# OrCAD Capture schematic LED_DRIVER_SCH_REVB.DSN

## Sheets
1 P02: P2W Led Driver Diagram
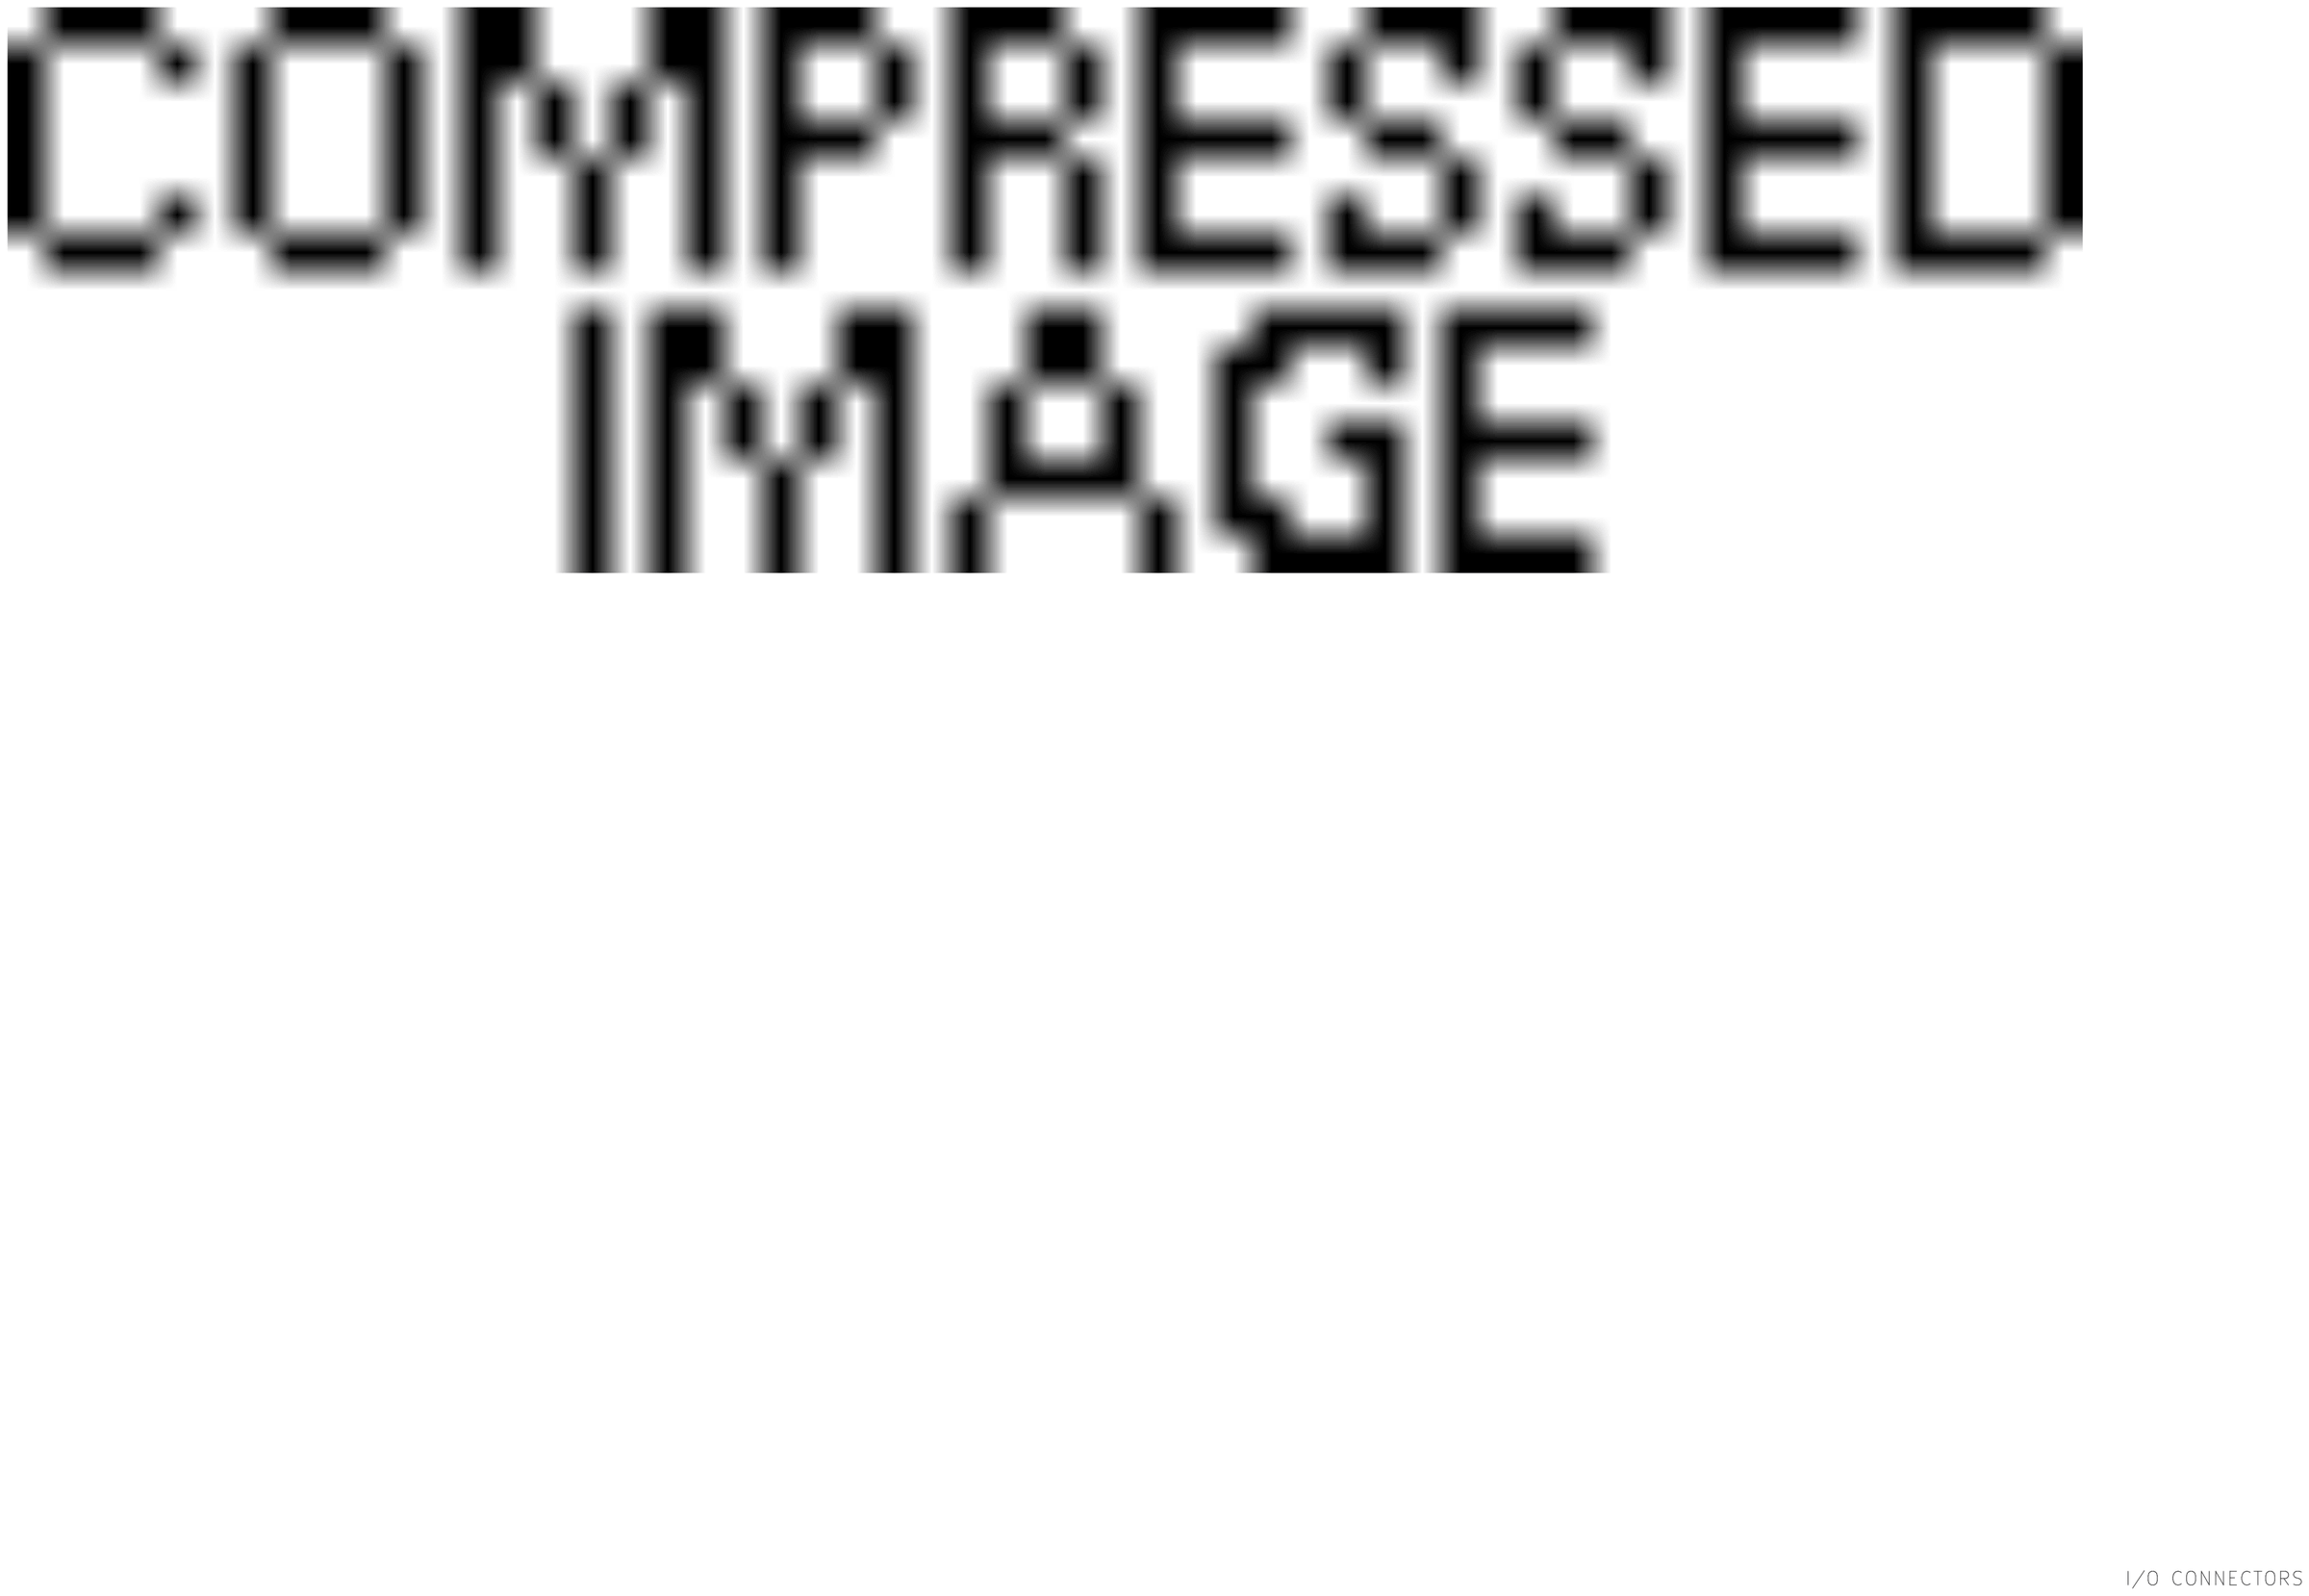
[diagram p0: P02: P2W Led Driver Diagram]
2 P04: P2W Led Driver Main: size D
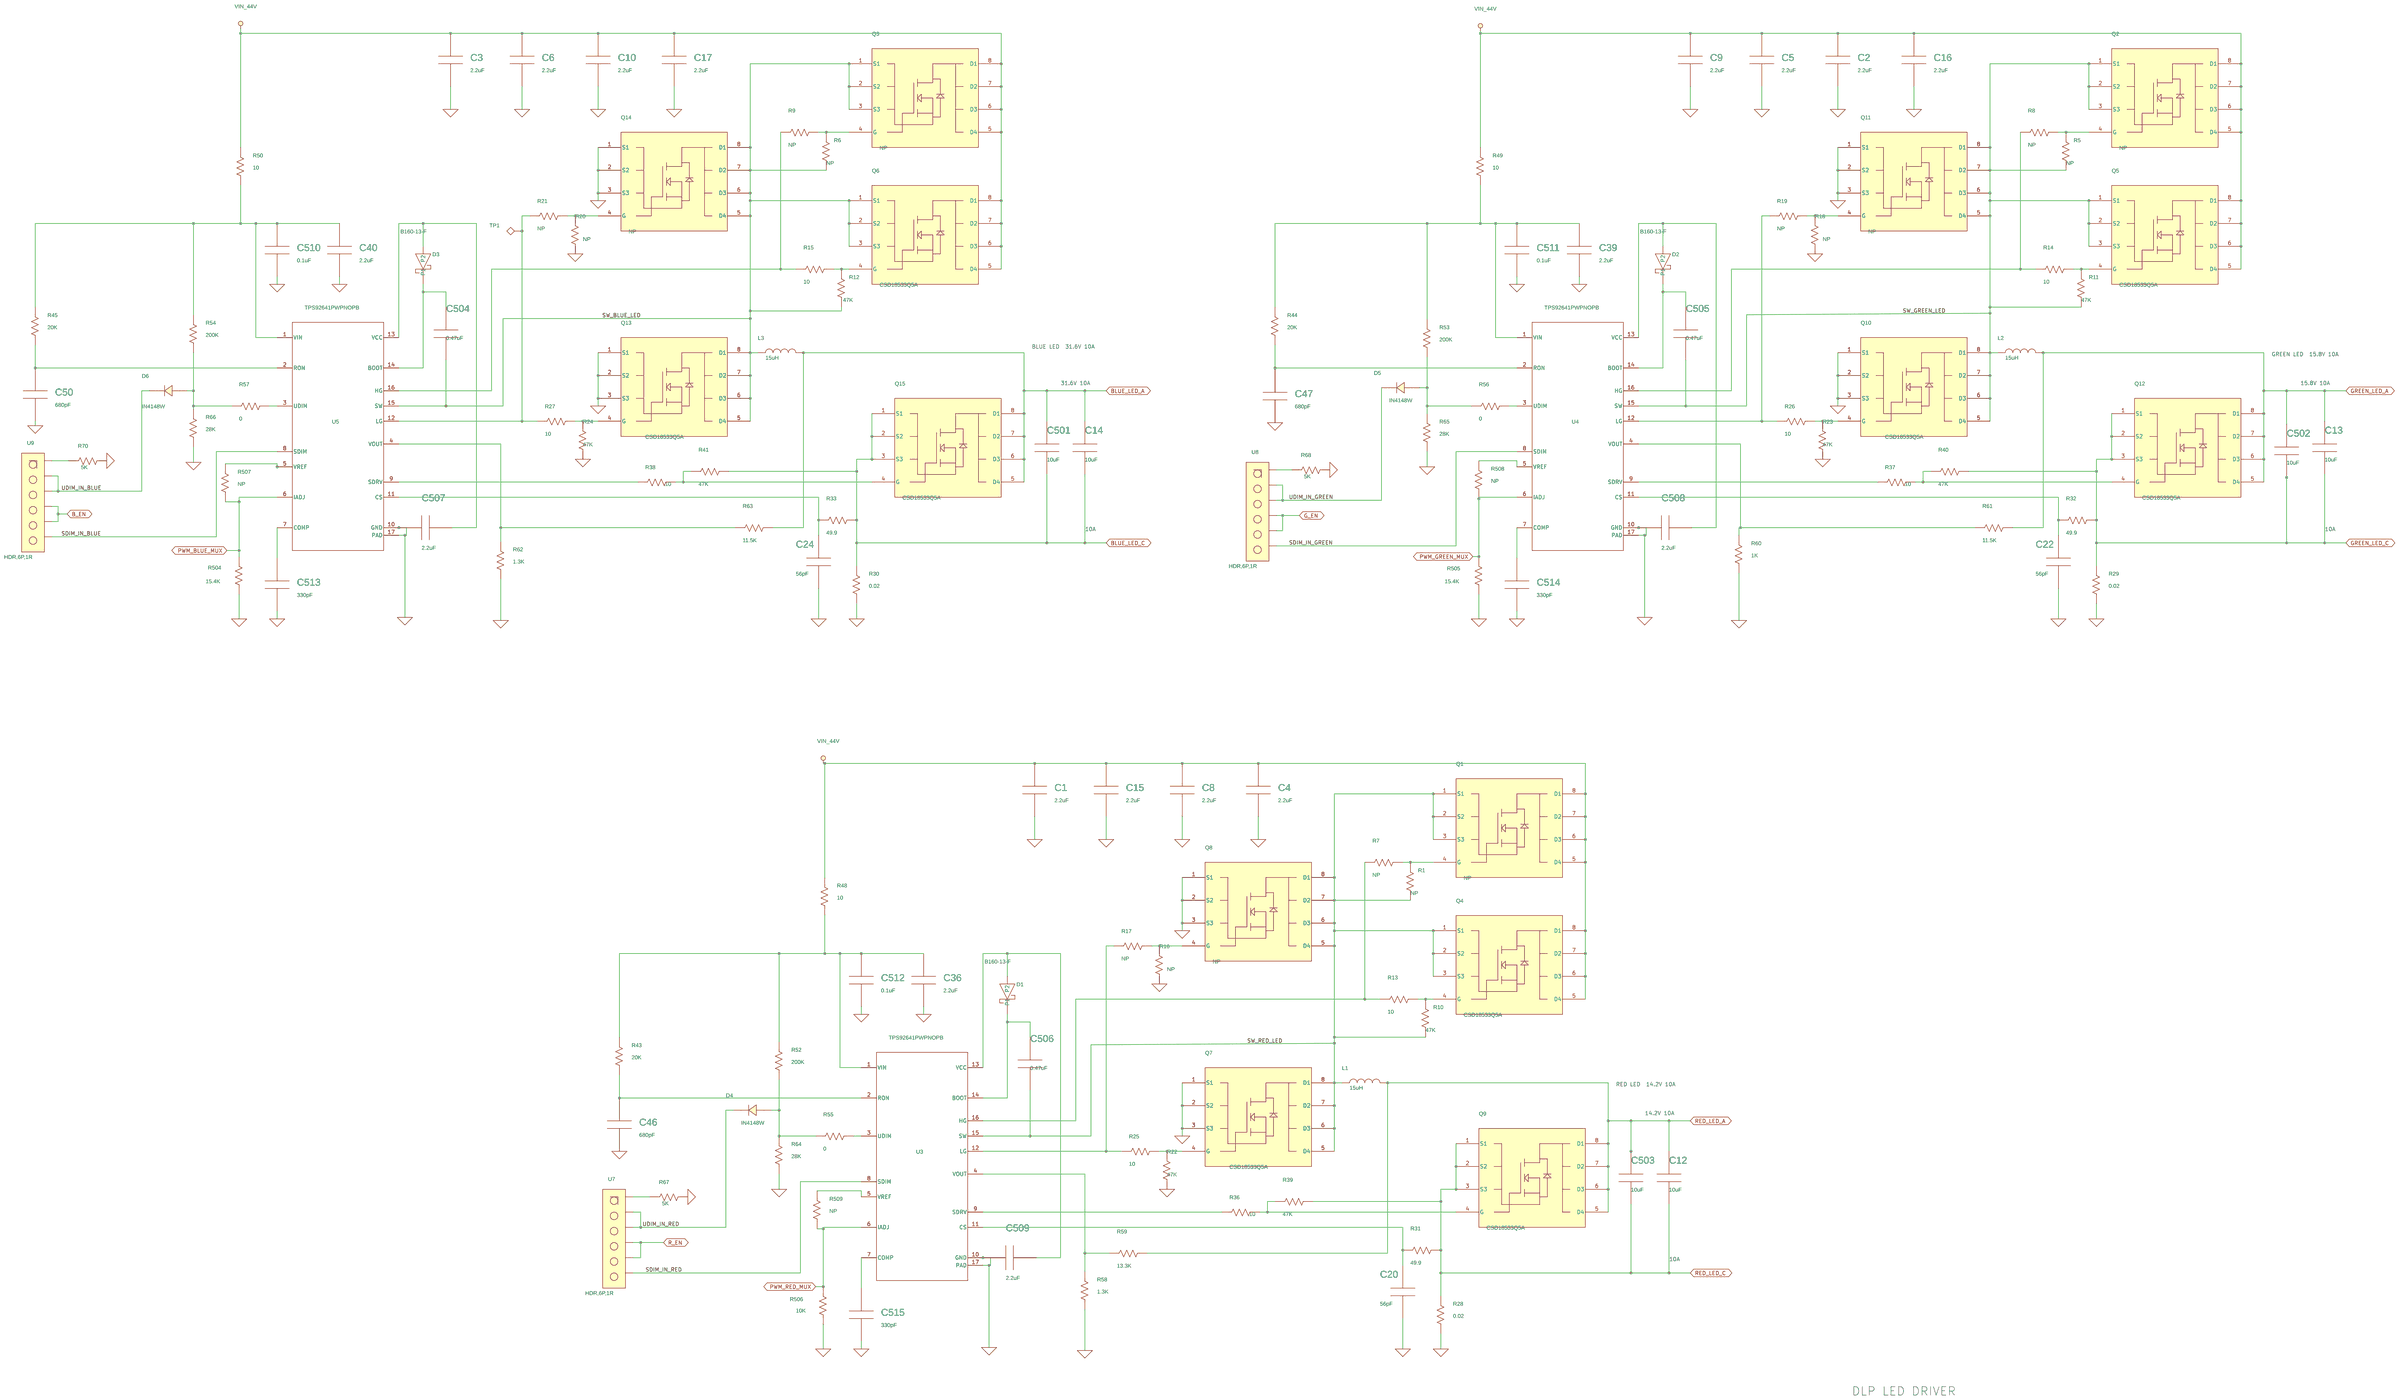
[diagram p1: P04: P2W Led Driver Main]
3 P03: P2W Led Driver Connectors: size D
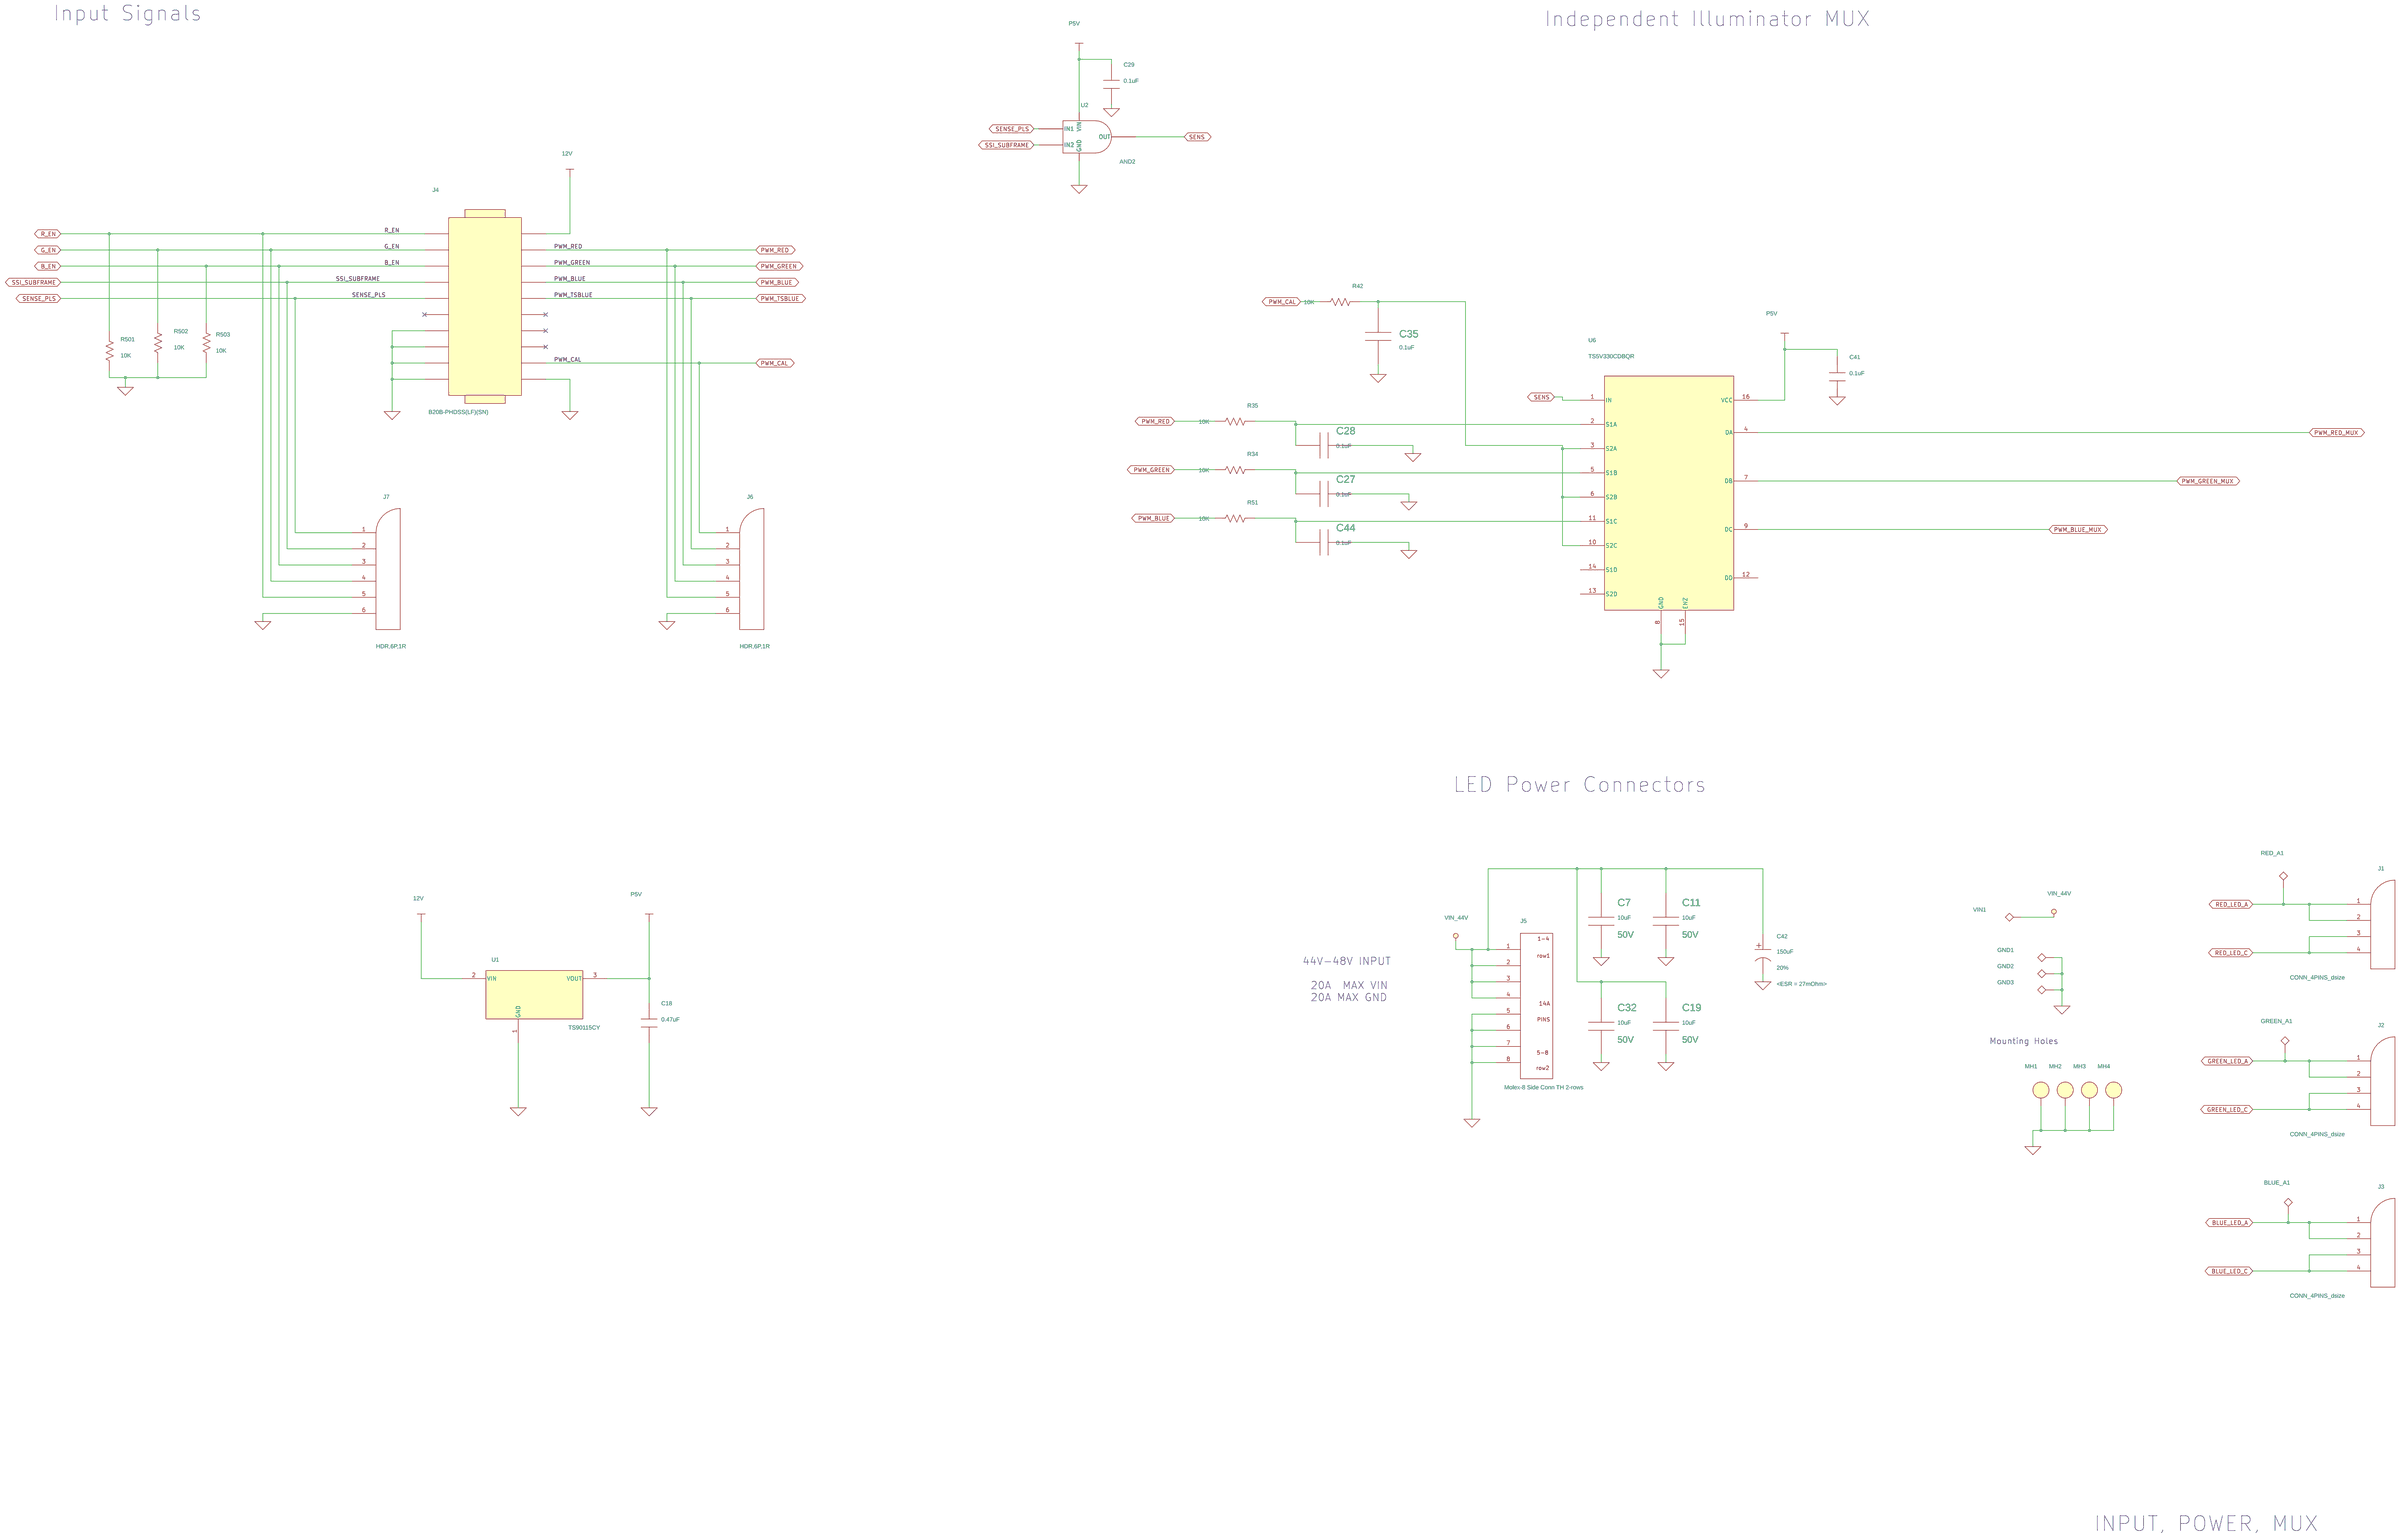
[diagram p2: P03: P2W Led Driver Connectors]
4 P01: P2W Led Driver Title Page: rev: A
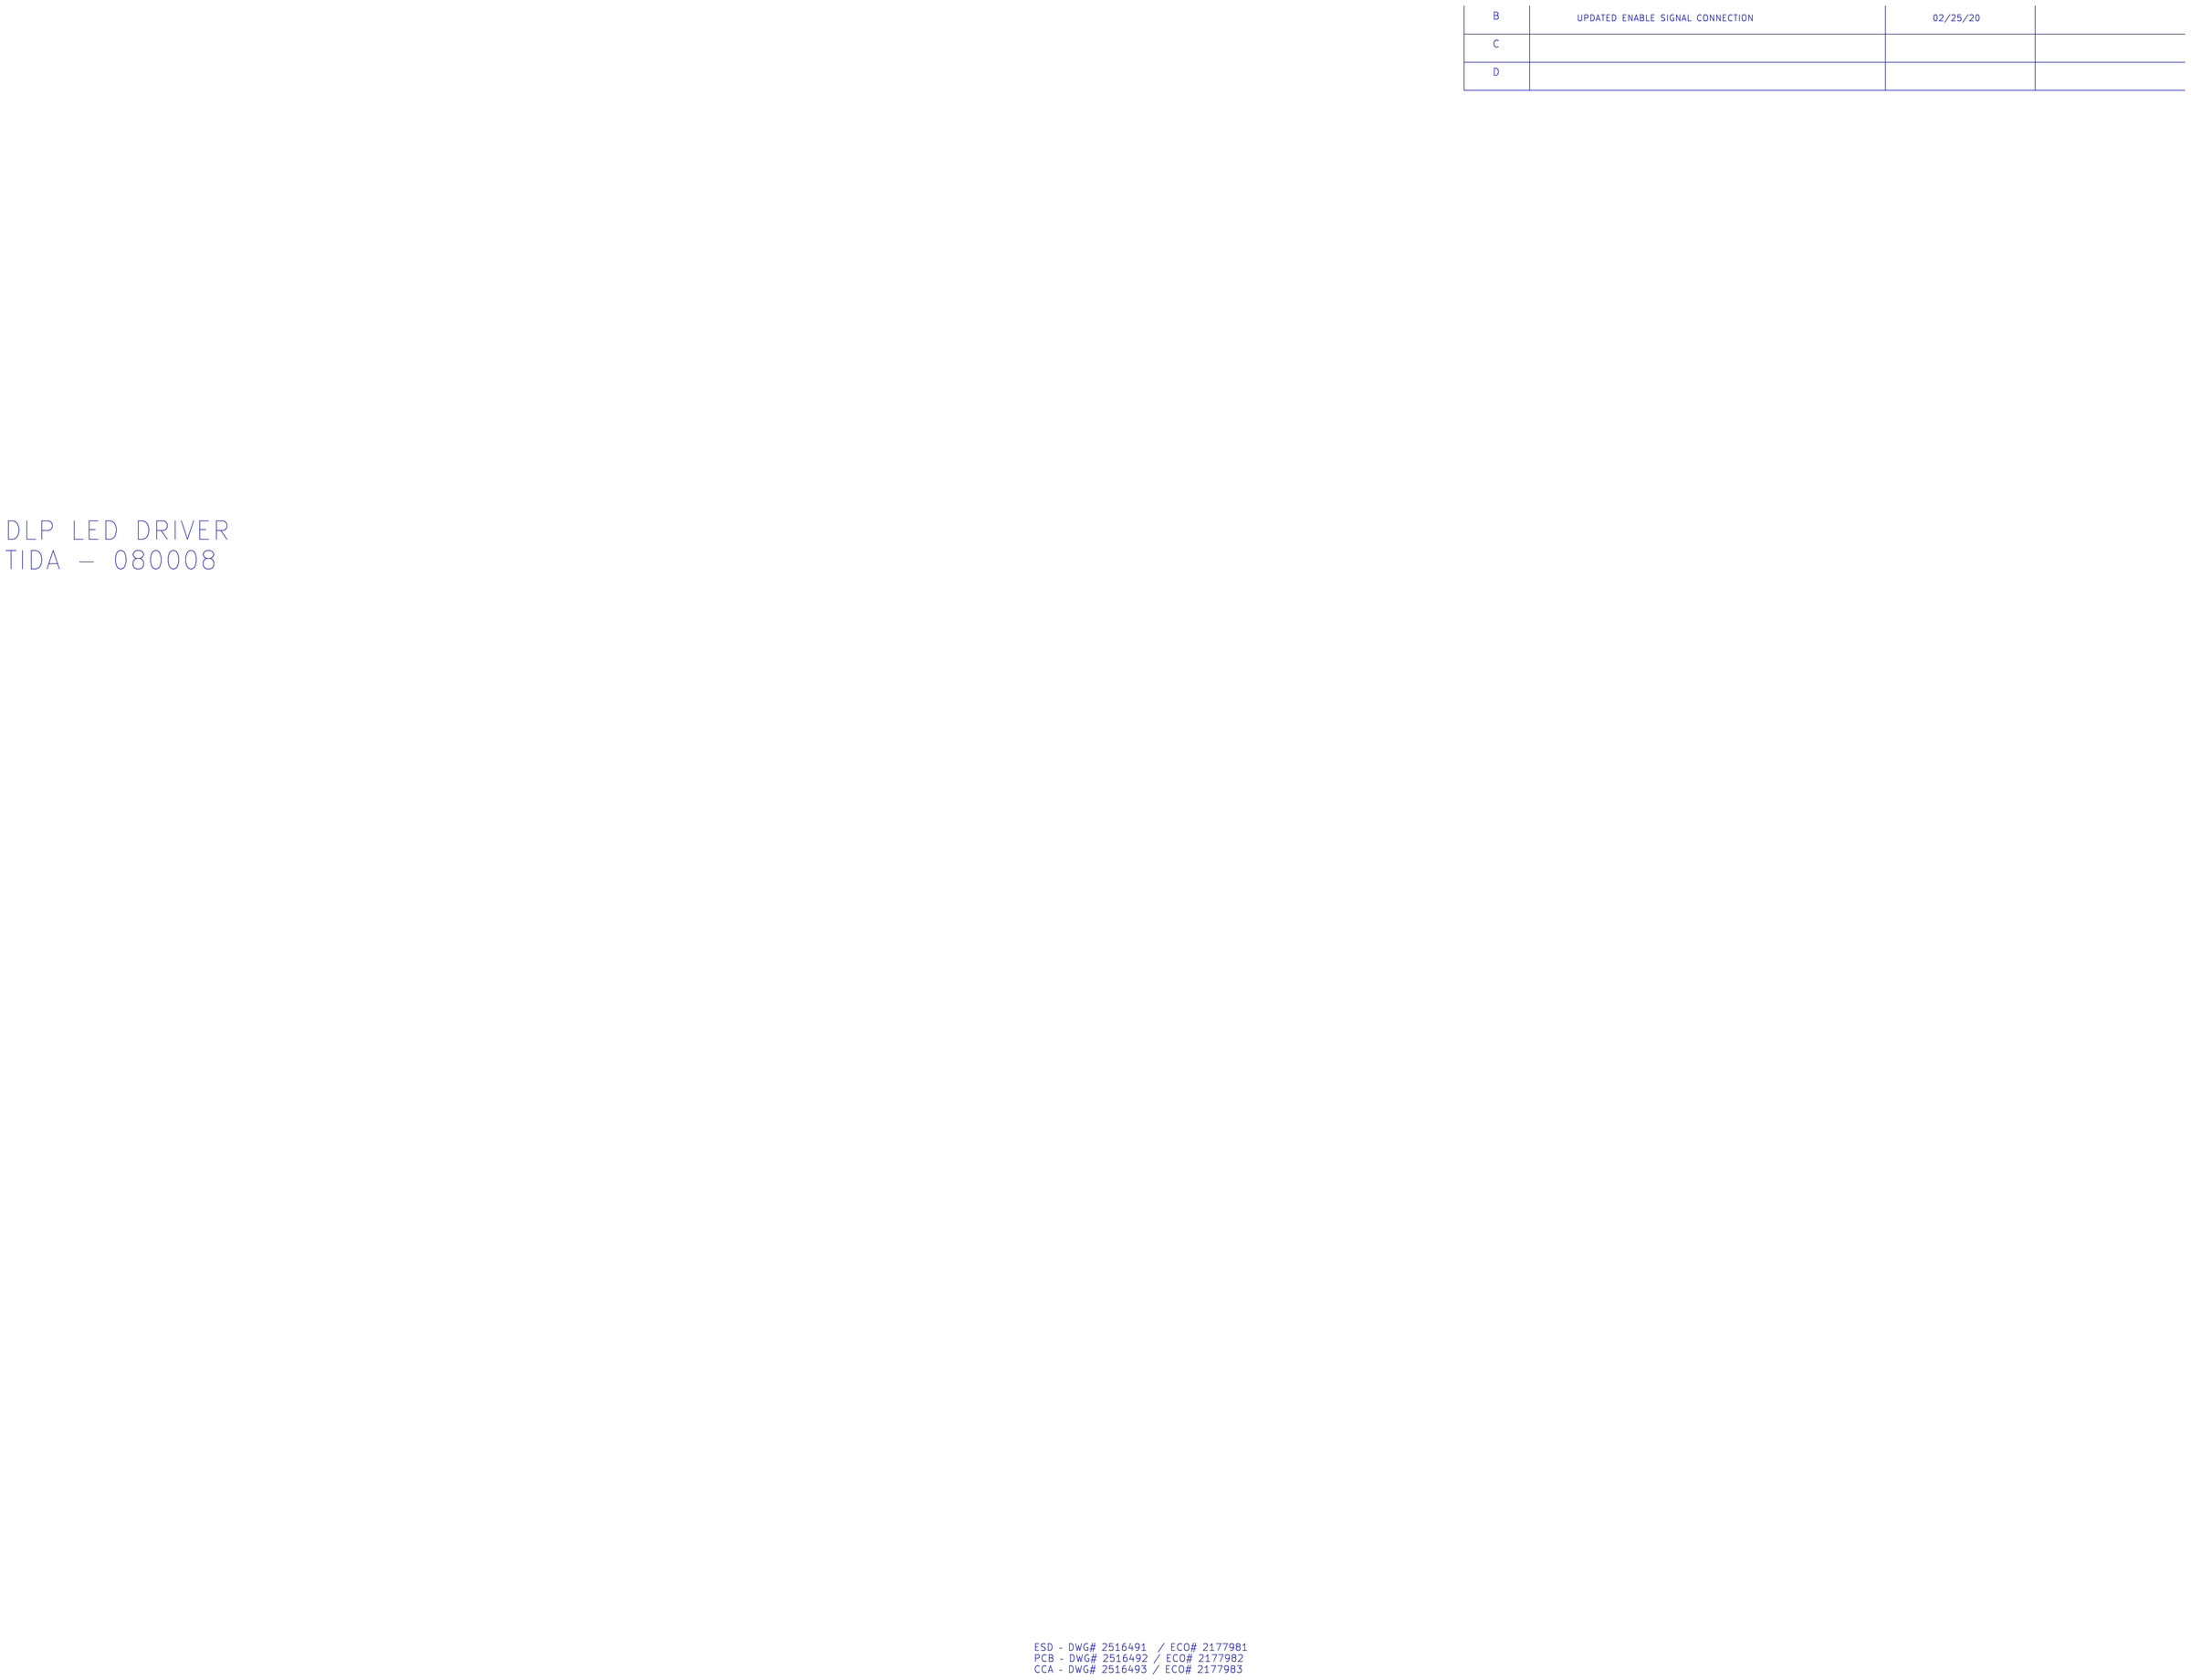
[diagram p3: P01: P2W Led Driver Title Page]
5 P05: P2W Led Driver Disclaimer

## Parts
sheet P03: P2W Led Driver Connectors
BLUE_A1  TEST POINT  [HOLE_PLATED_40mil_D_60mil_PAD]
C7  10uF  [1210]
C11  10uF  [1210]
C18  0.47uF  [0805]
C19  10uF  [1210]
C27  0.1uF  [0603]
C28  0.1uF  [0603]
C29  0.1uF  [0603]
C32  10uF  [1210]
C35  0.1uF  [0603]
C41  0.1uF  [0603]
C42  150uF  [CAPAE830X1050N]
C44  0.1uF  [0603]
GND1  TP_BLK  [KEYSTONE_TP_MINIATURE]
GND2  TP_BLK  [KEYSTONE_TP_MINIATURE]
GND3  TP_BLK  [KEYSTONE_TP_MINIATURE]
GREEN_A1  TEST POINT  [HOLE_PLATED_40mil_D_60mil_PAD]
J1  CONN_4PINS_dsize  [molex_1722981104]
J2  CONN_4PINS_dsize  [molex_1722981104]
J3  CONN_4PINS_dsize  [molex_1722981104]
J4  B20B-PHDSS(LF)(SN)  [JST_B20B-PHDSS]
J5  Molex-8 Side Conn TH 2-rows  [molex_1723161108]
J6  HDR,6P,1R  [SAMTEC_TSW-106-07-G-S]
J7  HDR,6P,1R  [SAMTEC_TSW-106-07-G-S]
MH1  MOUNTING_HOLE  [MH147-276GND]
MH2  MOUNTING_HOLE  [MH147-276GND]
MH3  MOUNTING_HOLE  [MH147-276GND]
MH4  MOUNTING_HOLE  [MH147-276GND]
R34  10K  [0402]
R35  10K  [0402]
R42  10K  [0402]
R51  10K  [0402]
R501  10K  [0402]
R502  10K  [0402]
R503  10K  [0402]
RED_A1  TEST POINT  [HOLE_PLATED_40mil_D_60mil_PAD]
U1  TS90115CY  [SOT89]
U2  AND2  [SOT-23-5]
U6  TS5V330CDBQR  [16-SSOP]
VIN1  TEST POINT  [HOLE_PLATED_40mil_D_60mil_PAD]
sheet P04: P2W Led Driver Main
C1  2.2uF  [1210]
C2  2.2uF  [1210]
C3  2.2uF  [1210]
C4  2.2uF  [1210]
C5  2.2uF  [1210]
C6  2.2uF  [1210]
C8  2.2uF  [1210]
C9  2.2uF  [1210]
C10  2.2uF  [1210]
C12  10uF  [1206]
C13  10uF  [1206]
C14  10uF  [1206]
C15  2.2uF  [1210]
C16  2.2uF  [1210]
C17  2.2uF  [1210]
C20  56pF  [0603]
C22  56pF  [0603]
C24  56pF  [0603]
C36  2.2uF  [1206]
C39  2.2uF  [1206]
C40  2.2uF  [1206]
C46  680pF  [0402]
C47  680pF  [0402]
C50  680pF  [0402]
C501  10uF  [1206]
C502  10uF  [1206]
C503  10uF  [1206]
C504  0.47uF  [0805]
C505  0.47uF  [0805]
C506  0.47uF  [0805]
C507  2.2uF  [0805]
C508  2.2uF  [0805]
C509  2.2uF  [0805]
C510  0.1uF  [0603]
C511  0.1uF  [0603]
C512  0.1uF  [0603]
C513  330pF  [0603]
C514  330pF  [0603]
C515  330pF  [0603]
D1  PAS,DIODE,SCHOTTKY,small  [DO-214AC]
D2  PAS,DIODE,SCHOTTKY,small  [DO-214AC]
D3  PAS,DIODE,SCHOTTKY,small  [DO-214AC]
D4  IN4148W  [SOT-23-3]
D5  IN4148W  [SOT-23-3]
D6  IN4148W  [SOT-23-3]
L1  15uH  [IND_XAL1010]
L2  15uH  [IND_XAL1010]
L3  15uH  [IND_XAL1010]
Q1  NP  [Surface_Mount_8-VSONP_5x6]
Q2  NP  [Surface_Mount_8-VSONP_5x6]
Q3  NP  [Surface_Mount_8-VSONP_5x6]
Q4  CSD18533Q5A  [Surface_Mount_8-VSONP_5x6]
Q5  CSD18533Q5A  [Surface_Mount_8-VSONP_5x6]
Q6  CSD18533Q5A  [Surface_Mount_8-VSONP_5x6]
Q7  CSD18533Q5A  [Surface_Mount_8-VSONP_5x6]
Q8  NP  [Surface_Mount_8-VSONP_5x6]
Q9  CSD18533Q5A  [Surface_Mount_8-VSONP_5x6]
Q10  CSD18533Q5A  [Surface_Mount_8-VSONP_5x6]
Q11  NP  [Surface_Mount_8-VSONP_5x6]
Q12  CSD18533Q5A  [Surface_Mount_8-VSONP_5x6]
Q13  CSD18533Q5A  [Surface_Mount_8-VSONP_5x6]
Q14  NP  [Surface_Mount_8-VSONP_5x6]
Q15  CSD18533Q5A  [Surface_Mount_8-VSONP_5x6]
R1  NP  [0603]
R5  NP  [0603]
R6  NP  [0603]
R7  NP  [0603]
R8  NP  [0603]
R9  NP  [0603]
R10  47K  [0603]
R11  47K  [0603]
R12  47K  [0603]
R13  10  [0603]
R14  10  [0603]
R15  10  [0603]
R16  NP  [0603]
R17  NP  [0603]
R18  NP  [0603]
R19  NP  [0603]
R20  NP  [0603]
R21  NP  [0603]
R22  47K  [0603]
R23  47K  [0603]
R24  47K  [0603]
R25  10  [0603]
R26  10  [0603]
R27  10  [0603]
R28  0.02  [2512]
R29  0.02  [2512]
R30  0.02  [2512]
R31  49.9  [2512]
R32  49.9  [2512]
R33  49.9  [2512]
R36  10  [0603]
R37  10  [0603]
R38  10  [0603]
R39  47K  [0603]
R40  47K  [0603]
R41  47K  [0603]
R43  20K  [0603]
R44  20K  [0603]
R45  20K  [0603]
R48  10  [1206]
R49  10  [1206]
R50  10  [1206]
R52  200K  [0402]
R53  200K  [0402]
R54  200K  [0402]
R55  0  [1206]
R56  0  [1206]
R57  0  [1206]
R58  1.3K  [2512]
R59  13.3K  [2512]
R60  1K  [2512]
R61  11.5K  [2512]
R62  1.3K  [2512]
R63  11.5K  [2512]
R64  28K  [0402]
R65  28K  [0402]
R66  28K  [0402]
R67  5K  [0402]
R68  5K  [0402]
R70  5K  [0402]
R504  15.4K  [0402]
R505  15.4K  [0402]
R506  10K  [0402]
R507  NP  [0402]
R508  NP  [0402]
R509  NP  [0402]
TP1  TEST POINT  [HOLE_PLATED_40mil_D_60mil_PAD]
U3  TPS92641PWPNOPB  [PWP0016A]
U4  TPS92641PWPNOPB  [PWP0016A]
U5  TPS92641PWPNOPB  [PWP0016A]
U7  HDR,6P,1R  [SAMTEC_TSW-106-07-G-S]
U8  HDR,6P,1R  [SAMTEC_TSW-106-07-G-S]
U9  HDR,6P,1R  [SAMTEC_TSW-106-07-G-S]

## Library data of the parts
BLUE_A1 GREEN_A1 RED_A1 = BF,HOLE,PLATED,TESTPIN: DNI: DNI; DigiKey: ---; DigiReel: ---; Family: board feature; Index PN: 377; Install: DNI; Lead Style: TH; Part Number: -- NOT A PART --; Type: hole,plated; Vendor: -- NOT A PART --
C7 C11 C19 C32 = PAS,CAP,NP,large: DigiKey: 587-2247-1-ND; DigiReel: 587-2247-6-ND; Family: passive; Lead Style: SMT; MFG: Taiyo Yuden; Material: X5R; P/D_NUM: UMK325BJ106KM-T; Part Number: UMK325BJ106KM-T; Part Specific: CAP CER 10UF 50V 10% X5R 1210; TOLERANCE: 10%; Type: capacitor; VENDOR: Taiyo Yuden; VPC: 50V; Voltage: 50V
C18 = CAP_NP_dsize: DigiKey: 1276-6482-2-ND; ESR: <ESR>; Family: passive; ICA_MFR_NAME: PANASONIC; ICA_PARTNUM: $$2121795$$ECJ3VB1E334K; Lead Style: SMT; MFG: Samsung Electro-Mechanics; Material: x7r; P/D_NUM: CL21B474KBFNNNG; Part Number: CL21B474KBFNNNG; Part Specific: CAP CER 4.7uF 50V 10% X7R 0805; TOLERANCE: 10%; Type: capacitor; VENDOR: Samsung Electro-Mechanics; VPC: 50V; Voltage: 50V
C27 C28 C35 C44 C510-C512 = PAS,CAP,NP,large: DigiKey: 311-1779-2-ND; Family: passive; Index PN: 1073; Lead Style: SMT; MFG: Yageo; Material: x7r; P/D_NUM: CC0603JRX7R9BB104; Part Number: CC0603JRX7R9BB104; Part Specific: CAP CER 0.1UF 50V 5% X7R 0603; TOLERANCE: 5%; Type: capacitor; VENDOR: Yageo; VPC: 50V; Voltage: 50V
C29 C41 = CAP_NP_dsize: DigiKey: 311-1779-2-ND; ESR: <ESR>; ICA_MFR_NAME: PANASONIC; ICA_PARTNUM: $$2121795$$ECJ3VB1E334K; Lead Style: SMT; MFG: Yageo; Material: x7r; P/D_NUM: CC0603JRX7R9BB104; Part Number: CC0603JRX7R9BB104; Part Specific: CAP CER 0.1UF 50V 5% X7R 0603; TOLERANCE: 5%; Type: capacitor; VENDOR: Yageo; VPC: 50V; Voltage: 50V
C42 = CAP_POL_dsize: DigiKey: 565-4779-2-ND; DigiReel: 565-4779-6-ND; ESR: <ESR = 27mOhm>; Family: passive; Index PN: Negative; Install: Y; Lead Style: SMT; MFG: Nippon Chemi-Con; Material: Hybrid; P/D_NUM: HHXC350ARA151MHA0G; Part Number: HHXC350ARA151MHA0G; Part Specific: CAP ALUM POLY 150UF 35V SMD; Pin Cnt: 2; RATING/TOLERANCE: 20%; VPC: 35V; Vendor: Nippon Chemi-Con; Voltage: 35V
GND1-GND3 = BF,HOLE,PLATED,TESTPIN: DigiKey: 5001K-ND; DigiReel: ---; Family: electro/mechanical; Index PN: 946; Install: Y; Lead Style: TH; MFG: Keystone; P/D_NUM: 5001; Part Number: 5001; Part Specific: TEST POINT PC MINI .040inD BLACK; Type: terminal; Vendor: Keystone
J1-J3 = CONN_4PINS_dsize: DigiKey: WM11578-ND; Lead Style: TH; MFG: Molex; P/D_NUM: 1722981104; Part Number: 1722981104; Part Specific: CONN HEADER VERT 4POS 3.5MM; Pin Cnt: 4; Pin Spacing: 3.5mm; Row Cnt: 2; Tolerance: 14A; Type: header; VENDOR: Molex; VPC: 400
J4 = CONN_2x10_dsize: MFG: JST; Part Specific: CONN HEADER VERT 20POS 2MM
J5 = CONN_8PINS_HiCurrent_dsize: DigiKey: WM11598-ND; Install: Y; Lead Style: TH; MFG: Molex; P/D_NUM: 1723161108; Part Number: 1723161108; Part Specific: CONN HEADER R/A 8POS 3.5MM; Pin Cnt: 8; Pin Spacing: 3.5mm; Row Cnt: 2; Tolerance: 14A; Type: header; VENDOR: Molex; VPC: 400
J6 J7 = CONN_6PINS_dsize: DigiKey: SAM1029-06-ND; DigiReel: SAM1029-06-ND; Family: Header; Install: Y; Lead Style: Through Hole; MFG: Samtec; P/D_NUM: TSW-106-07-G-S; Part Number: TSW-106-07-G-S; Part Specific: CONN HEADER VERT 6POS 2.54MM; Pin Cnt: 6; Pin Spacing: 0.100" (2.54mm); Row Cnt: 1; Tolerance: 1A; Type: Header; VENDOR: JST; VPC: 50V
MH1-MH4 = MOUNTING_HOLE: DNI: DNI; Part Number: -- NOT A PART --
R34 R35 R42 R51 R501-R503 = PAS,R,large: DigiKey: 541-10.0KLCT-ND; Family: passive; Index PN: 680; Lead Style: SMT; MFG: Vishay Dale; Material: chip; P/D_NUM: CRCW040210K0FKED; Part Number: CRCW040210K0FKED; Part Specific: RES 10K OHM 1/16W 1% 0402 SMD; Power: 1/16W; Tolerance: 1%; Type: resistor; VPC: 1/16W; Vendor: Vishay Dale
U1 = TS90115CY_RMG: MFG: Taiwan Semiconductor; Part Number: TS90115CY RMG; Part Specific: IC REG LINEAR 5V 250MA SOT89
U2 = AND2_1: DigiKey: 296-1113-2-ND; MFG: Texas Instruments; P/D_NUM: SN74AHCT1G08DBVR; Part Number: SN74AHCT1G08DBVR; Part Specific: IC GATE AND 1CH 2-INP SOT23-5
U6 = TS5V330C: DigiKey: 296-25417-1-ND; MFG: Texas Instruments; Part Specific: IC VIDEO SWITCH QUAD SPDT 16SSOP
VIN1 = BF,HOLE,PLATED,TESTPIN: DNI: DNI; DigiKey: ---; DigiReel: ---; Family: board feature; Index PN: 377; Install: DNI; Lead Style: TH; Part Number: -- NOT A PART --; Vendor: -- NOT A PART --
C1-C6 C8-C10 C15-C17 C36 C39 C40 = PAS,CAP,NP,large: DigiKey: 1276-2723-2-ND; Family: passive; Index PN: 1073; Lead Style: SMT; MFG: Samsung Electro-Mechanics; Material: x5r; P/D_NUM: CL31A225KB9LNNC; Part Number: CL31A225KB9LNNC; Part Specific: CAP CER 2.2UF 50V 10% X5R 1206; TOLERANCE: 10%; Type: capacitor; VENDOR: Samsung Electro-Mechanics; VPC: 50V; Voltage: 50V
C12-C14 C501-C503 = PAS,CAP,NP,large: DigiKey: 1276-6736-2-ND; Family: passive; Index PN: 1073; Lead Style: SMT; MFG: Samsung Electro-Mechanics; Material: x5r; P/D_NUM: CL31A106MBHNNNE; Part Number: CL31A106MBHNNNE; Part Specific: CAP CER 10UF 50V X5R 1206; TOLERANCE: 10%; Type: capacitor; VENDOR: Samsung Electro-Mechanics; VPC: 50V; Voltage: 50V
C20 C22 C24 = PAS,CAP,NP,large: DigiKey: 399-7939-2-ND; Family: passive; Index PN: 1073; Lead Style: SMT; MFG: Kemet; P/D_NUM: C0603C560F5GACTU; Part Number: C0603C560F5GACTU; Part Specific: CAP CER 56PF 50V 1% 0603; TOLERANCE: 1%; Type: capacitor; VENDOR: Kemet; VPC: 50V; Voltage: 50V
C46 C47 C50 = PAS,CAP,NP,large: DigiKey: 1276-1583-1-ND; Family: passive; Index PN: 1073; Lead Style: SMT; MFG: Samsung Electro-Mechanics; Material: x7r; P/D_NUM: CL05B681KB5NNNC; Part Number: CL05B681KB5NNNC; Part Specific: CAP CER 680pF 50V 10% X7R 0402; TOLERANCE: 10%; Type: capacitor; VENDOR: Samsung Electro-Mechanics; VPC: 50V; Voltage: 50V
C504-C506 = PAS,CAP,NP,large: DigiKey: 1276-6482-2-ND; Family: passive; Index PN: 1073; Lead Style: SMT; MFG: Samsung Electro-Mechanics; Material: x7r; P/D_NUM: CL21B474KBFNNNG; Part Number: CL21B474KBFNNNG; Part Specific: CAP CER 4.7uF 50V 10% X7R 0805; TOLERANCE: 10%; Type: capacitor; VENDOR: Samsung Electro-Mechanics; VPC: 50V; Voltage: 50V
C507-C509 = PAS,CAP,NP,large: DigiKey: 1276-2953-2-ND; Family: passive; Index PN: 1073; Lead Style: SMT; MFG: Samsung Electro-Mechanics; Material: x7r; P/D_NUM: CL21B225KAFNFNE; Part Number: CL21B225KAFNFNE; Part Specific: CAP CER 2.2UF 25V 10% X7R 0805; TOLERANCE: 10%; Type: capacitor; VENDOR: Samsung Electro-Mechanics; VPC: 25V; Voltage: 25V
C513-C515 = PAS,CAP,NP,large: DigiKey: C0603C331F3HAC7867-ND; Family: passive; Index PN: 1073; Lead Style: SMT; MFG: Kemet; Material: x8r; P/D_NUM: C0603C331F3HAC7867; Part Number: C0603C331F3HAC7867; Part Specific: CAP CER 330PF 25V 1% X8R 0603; TOLERANCE: 1%; Type: capacitor; VENDOR: Kemet; VPC: 25V; Voltage: 25V
D1-D3 = PAS,DIODE,SCHOTTKY,small: DigiKey: B160-FDITR-ND; DigiReel: B160-FDITR-ND; Lead Style: SMT; MFG: Diodes Inc; P/D_NUM: B160-13-F; Part Number: B160-13-F; Part Specific: DIODE SCHOTTKY 60V 1A SMA; Type: diode,schottky; VENDOR: Diodes Inc; VPC: 1A; Voltage: 60V
D4-D6 = DIODE: DigiKey: MMBD4448-FDICT-ND; Lead Style: SMT; MFG: Diodes Inc; P/D_NUM: MMBD4448-7-F; Part Number: MMBD4448-7-F; Part Specific: DIODE GEN PURP 75V 250MA SOT23-3; Type: Standard; VENDOR: Diodes Inc; VPC: 250 mA; Voltage: 75V
L1-L3 = PAS,INDUCTOR,_large: Family: passive; MFG: Sumida; P/D_NUM: XAL1010-153MEB; Part Number: XAL1010-153MEB; Part Specific: Fixed Inductors 15uH 20% 13.8A 18.6mOhms AEC-Q200; TOLERANCE: 20%; Type: Inductor; VENDOR: Coilcraft
Q1-Q3 Q8 Q11 Q14 = ANA,FET,CSD17556Q5B: DigiKey: 296-35027-1-ND; DigiReel: 296-35027-1-ND; Install: Y; MFG: Texas Instruments; P/D_NUM: CSD18533Q5A; Part Number: CSD18533Q5A; Part Specific: MOSFET N-CH 60V 17A 8SON; VENDOR: Texas Instruments; VPC: 17A; Voltage: 60V
Q4-Q7 Q9 Q10 Q12 Q13 Q15 = ANA,FET,CSD17556Q5B: DigiKey: 296-35027-1-ND; DigiReel: 296-35027-1-ND; Install: Y; MFG: Texas Instruments; Part Specific: MOSFET N-CH 60V 17A 8SON; VENDOR: Texas Instruments; VPC: 17A; Voltage: 60V
R1 R5 R6 R10-R12 R16 R18 R20 R22-R24 R39-R41 = PAS,R,large: DigiKey: 311-47.0KHRTR-ND; Family: passive; Index PN: 680; Lead Style: SMT; MFG: Yageo; Material: chip; P/D_NUM: RC0603FR-0747KL; Part Number: RC0603FR-0747KL; Part Specific: RES 47K OHM 1/10W 1% 0603 SMD; Power: 1/10W; Tolerance: 1%; Type: resistor; VPC: 1/10W; Vendor: Yageo
R7-R9 R13-R15 R17 R19 R21 R25-R27 R36-R38 = PAS,R,large: DigiKey: RMCF0603JG10R0TR-ND; Family: passive; Index PN: 680; Lead Style: SMT; MFG: Vishay Dale; Material: chip; P/D_NUM: RMCF0603JG10R0; Part Number: RMCF0603JG10R0; Part Specific: RES 10 OHM 5% 1/10W 0603; Power: 1/10W; Tolerance: ±5%; Type: resistor; VPC: 1/10W; Vendor: Stackpole Electronics Inc
R28-R30 = PAS,R,large: DigiKey: CSRN2512FK20L0CT-ND; Family: passive; Index PN: 680; Lead Style: SMT; MFG: Stackpole Electronics Inc; Material: chip; P/D_NUM: CSRN2512FK20L0; Part Number: CSRN2512FK20L0; Part Specific: RES 0.02 OHM 1% 2W 2512; Power: 2W; Tolerance: 1%; Type: resistor; VPC: 2W; Vendor: Yageo
R31-R33 = PAS,R,large: DigiKey: RCL49.9ETR-ND; Family: passive; Index PN: 680; Lead Style: SMT; MFG: Vishay Dale; Material: chip; P/D_NUM: RCL122549R9FKEG; Part Number: RCL122549R9FKEG; Part Specific: RES 49.9 OHM 2W 1% 2512 SMD; Power: 2W; Tolerance: 1%; Type: resistor; VPC: 2W; Vendor: Vishay Dale
R43-R45 = PAS,R,large: DigiKey: 311-20.0KHRTR-ND; Family: passive; Index PN: 680; Lead Style: SMT; MFG: Yageo; Material: chip; P/D_NUM: RC0603FR-072KL; Part Number: RC0603FR-072KL; Part Specific: RES SMD 20K OHM 1% 1/10W 0603; Power: 1/10W; Tolerance: 1%; Type: resistor; VPC: 1/10W; Vendor: Yageo
R48-R50 = PAS,R,large: DigiKey: 541-10.0FCT-ND; Family: passive; Index PN: 680; Lead Style: SMT; MFG: Vishay Dale; Material: chip; P/D_NUM: CRCW120610R0FKEA; Part Number: CRCW120610R0FKEA; Part Specific: RES 10 OHM 1/4W 1% 1206 SMD; Power: 1/4W; Tolerance: 1%; Type: resistor; VPC: 1/4W; Vendor: Vishay Dale
R52-R54 = PAS,R,large: DigiKey: P200KLTR-ND; Family: passive; Index PN: 680; Lead Style: SMT; MFG: Panasonic; Material: chip; P/D_NUM: ERJ-2RKF2003X; Part Number: ERJ-2RKF2003X; Part Specific: RES 200K OHM 1/10W 1% 0402 SMD; Power: 1/10W; Tolerance: 1%; Type: resistor; VPC: 1/10W; Vendor: Panasonic
R55-R57 = PAS,R,large: DigiKey: 541-1890-1-ND; Family: passive; Index PN: 680; Lead Style: SMD; MFG: Vishay Dale; Material: chip; P/D_NUM: RCG12060000Z0EA; Part Number: RCG12060000Z0EA; Part Specific: RES 0 OHM 1/4W 1% 1206 SMD; Power: 1/4W; Type: resistor; VPC: 1/4W; Vendor: Vishay Dale
R58 R62 = PAS,R,large: DigiKey: RMCF2512FT1K30TR-ND; Family: passive; Index PN: 680; Lead Style: SMT; MFG: TE Connectivity; Material: chip; P/D_NUM: CRGCQ2512F100K; Part Number: RMCF2512FT1K30; Part Specific: RES 1.3K OHM 1% 1W 2512; Power: 1W; Tolerance: 1%; Type: resistor; VPC: 1W; Vendor: TE Connectivity
R59 R61 R63 = PAS,R,large: DigiKey: 541-11.5KAFTR-ND; Family: passive; Index PN: 680; Lead Style: SMT; MFG: Vishay Dale; Material: chip; P/D_NUM: CRCW251211K5FKEG; Part Number: CRCW251211K5FKEG; Part Specific: RES 11.5K OHM 1W 1% 2512 SMD; Power: 1W; Tolerance: 1%; Type: resistor; VPC: 1W; Vendor: Vishay Dale
R60 = PAS,R,large: DigiKey: RMCF2512FT1K00TR-ND; Family: passive; Index PN: 680; Lead Style: SMT; MFG: TE Connectivity; Material: chip; P/D_NUM: RMCF2512FT1K00; Part Number: RMCF2512FT1K00; Part Specific: RES 1K OHM 1% 1W 2512; Power: 1W; Tolerance: 1%; Type: resistor; VPC: 1W; Vendor: TE Connectivity
R64-R66 = PAS,R,large: DigiKey: 541-28.0KYCT-ND; Family: passive; Index PN: 680; Lead Style: SMT; MFG: Vishay Dale; Material: chip; P/D_NUM: CRCW040228K0FKEDHP; Part Number: CRCW040228K0FKEDHP; Part Specific: RES 28K OHM 1/5W 1% 0402 SMD; Power: 1/5W; Tolerance: 1%; Type: resistor; VPC: 1/5W; Vendor: Vishay Dale
R67 R68 R70 = PAS,R,large: DigiKey: RC0402FR-075KL-ND; Family: passive; Index PN: 680; Lead Style: SMT; MFG: Yageo; Material: chip; P/D_NUM: RC0402FR-075KL; Part Number: RC0402FR-075KL; Part Specific: RES 5K OHM 1/16W 1% 0402 SMD; Power: 1/16W; Tolerance: 1%; Type: resistor; VPC: 1/16W; Vendor: Yageo
R504 R505 = PAS,R,large: DigiKey: YAG2992CT-ND; Family: passive; Index PN: 680; Lead Style: SMT; MFG: Yageo; Material: chip; P/D_NUM: RC0402FR-0715K4L; Part Number: RC0402FR-0715K4L; Part Specific: RES SMD 15.4K OHM 1% 1/16W 0402; Power: 1/16W; Tolerance: 1%; Type: resistor; VPC: 1/16W; Vendor: Yageo
R506 = PAS,R,large: DigiKey: RMCF0402FT10K0CT-ND; Family: passive; Index PN: 680; Lead Style: SMT; MFG: Yageo; Material: chip; P/D_NUM: RMCF0402FT10K0; Part Number: RMCF0402FT10K0; Part Specific: RES 10K OHM 1% 1/16W 0402; Power: 1/16W; Tolerance: 1%; Type: resistor; VPC: 1/16W; Vendor: Yageo
R507-R509 = PAS,R,large: Family: passive; Index PN: 680; Lead Style: SMT; MFG: Yageo; Material: chip; Part Specific: RES 5K OHM 1/16W 1% 0402 SMD; Power: 1/16W; Tolerance: 1%; Type: resistor; VPC: 1/16W; Vendor: Yageo
TP1 = BF,HOLE,PLATED,TESTPIN: MFG: Keystone; P/D_NUM: 5000; Part Number: 5000; Part Specific: PC TEST POINT MINIATURE RED
U3-U5 = TPS92641PWPNOPB: MFG: Texas Instruments; Part Number: TPS92641; Part Specific: Synchronous Buck Controllers; VENDOR: Texas Instruments
U7-U9 = EM,HDR,6P: MFG: Samtec; Part Number: TSW-106-07-G-S; Part Specific: CONN HEADER VERT 6POS 2.54MM

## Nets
12V: J4.1 U1.2(VIN)
DGND: C1.1(P) C2.1(P) C3.1(P) C4.1(P) C5.1(P) C6.1(P) C7.2(N) C8.1(P) C9.1(P) C10.1(P) C11.2(N) C15.1(P) C16.1(P) C17.1(P) C18.2 C19.2(N) C20.2(N) C22.2(N) C24.2(N) C27.1(P) C28.1(P) C29.2 C32.2(N) C35.2(N) C36.1(P) C39.1(P) C40.1(P) C41.2 C42.2 C44.1(P) C46.2(N) C47.2(N) C50.2(N) C507.1(P) C508.1(P) C509.1(P) C510.1(P) C511.1(P) C512.1(P) C513.2(N) C514.2(N) C515.2(N) GND1.1(P1) GND2.1(P1) GND3.1(P1) J4.14 J4.16 J4.18 J4.19 J4.20 J5.5 J5.6 J5.7 J5.8 J6.6 J7.6 MH1.1 MH2.1 MH3.1 MH4.1 Q7.1(S1) Q7.2(S2) Q7.3(S3) Q8.1(S1) Q8.2(S2) Q8.3(S3) Q10.1(S1) Q10.2(S2) Q10.3(S3) Q11.1(S1) Q11.2(S2) Q11.3(S3) Q13.1(S1) Q13.2(S2) Q13.3(S3) Q14.1(S1) Q14.2(S2) Q14.3(S3) R16.1(N1) R18.1(N1) R20.1(N1) R22.1(N1) R23.1(N1) R24.1(N1) R28.1(N1) R29.1(N1) R30.1(N1) R58.1(N1) R60.1(N1) R62.1(N1) R64.1(N1) R65.1(N1) R66.1(N1) R67.1(N1) R68.1(N1) R70.1(N1) R501.2(N2) R502.2(N2) R503.2(N2) R504.1(N1) R505.1(N1) R506.1(N1) U1.1(GND) U2.3(GND) U3.10(GND) U3.17(PAD) U4.10(GND) U4.17(PAD) U5.10(GND) U5.17(PAD) U6.8(GND) U6.15(ENZ)
P5V: C18.1 C29.1 C41.1 U1.3(VOUT) U2.5(VIN) U6.16(VCC)
VIN_44V: C1.2(N) C2.2(N) C3.2(N) C4.2(N) C5.2(N) C6.2(N) C7.1(P) C8.2(N) C9.2(N) C10.2(N) C11.1(P) C15.2(N) C16.2(N) C17.2(N) C19.1(P) C32.1(P) C42.1 J5.1 J5.2 J5.3 J5.4 Q1.5(D4) Q1.6(D3) Q1.7(D2) Q1.8(D1) Q2.5(D4) Q2.6(D3) Q2.7(D2) Q2.8(D1) Q3.5(D4) Q3.6(D3) Q3.7(D2) Q3.8(D1) Q4.5(D4) Q4.6(D3) Q4.7(D2) Q4.8(D1) Q5.5(D4) Q5.6(D3) Q5.7(D2) Q5.8(D1) Q6.5(D4) Q6.6(D3) Q6.7(D2) Q6.8(D1) R48.2(N2) R49.2(N2) R50.2(N2) VIN1.1(P1)
B_EN: J4.6 J7.3 R503.1(N1) U9.4 U9.5
BLUE_LED_A: BLUE_A1.1(P1) C14.2(N) C501.2(N) J3.1 J3.2 L3.2 Q15.5(D4) Q15.6(D3) Q15.7(D2) Q15.8(D1) R63.1(N1)
BLUE_LED_C: C14.1(P) C501.1(P) J3.3 J3.4 Q15.1(S1) Q15.2(S2) Q15.3(S3) R30.2(N2) R33.1(N1) R41.1(N1)
G_EN: J4.4 J7.4 R502.1(N1) U8.4 U8.5
GREEN_LED_A: C13.2(N) C502.2(N) GREEN_A1.1(P1) J2.1 J2.2 L2.2 Q12.5(D4) Q12.6(D3) Q12.7(D2) Q12.8(D1) R61.1(N1)
GREEN_LED_C: C13.1(P) C502.1(P) J2.3 J2.4 Q12.1(S1) Q12.2(S2) Q12.3(S3) R29.2(N2) R32.1(N1) R40.1(N1)
PWM_BLUE: J4.7 J6.3 R51.2(N2)
PWM_BLUE_MUX: R504.2(N2) R507.1(N1) U5.6(IADJ) U6.9(DC)
PWM_CAL: J4.17 J6.1 R42.2(N2)
PWM_GREEN: J4.5 J6.4 R34.2(N2)
PWM_GREEN_MUX: R505.2(N2) R508.1(N1) U4.6(IADJ) U6.7(DB)
PWM_RED: J4.3 J6.5 R35.2(N2)
PWM_RED_MUX: R506.2(N2) R509.1(N1) U3.6(IADJ) U6.4(DA)
PWM_TSBLUE: J4.9 J6.2
R_EN: J4.2 J7.5 R501.1(N1) U7.4 U7.5
RED_LED_A: C12.2(N) C503.2(N) J1.1 J1.2 L1.2 Q9.5(D4) Q9.6(D3) Q9.7(D2) Q9.8(D1) R59.1(N1) RED_A1.1(P1)
RED_LED_C: C12.1(P) C503.1(P) J1.3 J1.4 Q9.1(S1) Q9.2(S2) Q9.3(S3) R28.2(N2) R31.1(N1) R39.1(N1)
SDIM_IN_BLUE: U5.8(SDIM) U9.6
SDIM_IN_GREEN: U4.8(SDIM) U8.6
SDIM_IN_RED: U3.8(SDIM) U7.6
SENS: U2.4(OUT) U6.1(IN)
SENSE_PLS: J4.10 J7.1 U2.1(IN1)
SSI_SUBFRAME: J4.8 J7.2 U2.2(IN2)
SW_BLUE_LED: C504.1(P) L3.1 Q3.1(S1) Q3.2(S2) Q3.3(S3) Q6.1(S1) Q6.2(S2) Q6.3(S3) Q13.5(D4) Q13.6(D3) Q13.7(D2) Q13.8(D1) Q14.5(D4) Q14.6(D3) Q14.7(D2) Q14.8(D1) R6.1(N1) R12.1(N1) U5.15(SW)
SW_GREEN_LED: C505.1(P) L2.1 Q2.1(S1) Q2.2(S2) Q2.3(S3) Q5.1(S1) Q5.2(S2) Q5.3(S3) Q10.5(D4) Q10.6(D3) Q10.7(D2) Q10.8(D1) Q11.5(D4) Q11.6(D3) Q11.7(D2) Q11.8(D1) R5.1(N1) R11.1(N1) U4.15(SW)
SW_RED_LED: C506.1(P) L1.1 Q1.1(S1) Q1.2(S2) Q1.3(S3) Q4.1(S1) Q4.2(S2) Q4.3(S3) Q7.5(D4) Q7.6(D3) Q7.7(D2) Q7.8(D1) Q8.5(D4) Q8.6(D3) Q8.7(D2) Q8.8(D1) R1.1(N1) R10.1(N1) U3.15(SW)
UDIM_IN_BLUE: D6.1(K) U9.2 U9.3
UDIM_IN_GREEN: D5.1(K) U8.2 U8.3
UDIM_IN_RED: D4.1(K) U7.2 U7.3
N16618528: C35.1(P) R42.1(N1) U6.3(S2A) U6.6(S2B) U6.10(S2C)
N16758628: C40.2(N) C510.2(N) R45.2(N2) R50.1(N1) R54.2(N2) U5.1(VIN)
N16758698: C24.1(P) R33.2(N2) U5.11(CS)
N16758720: R9.2(N2) R15.2(N2) U5.16(HG)
N16758730: C50.1(P) R45.1(N1) U5.2(RON)
N16758738: C504.2(N) D3.1(P1) U5.14(BOOT)
N16758742: R21.2(N2) R27.2(N2) TP1.1(P1) U5.12(LG)
N16758746: R57.1(N1) U5.3(UDIM)
N16758748: D6.2(A) R54.1(N1) R57.2(N2) R66.2(N2)
N16758754: R62.2(N2) R63.2(N2) U5.4(VOUT)
N16758760: C507.2(N) D3.2(P2) U5.13(VCC)
N16759526: Q13.4(G) R24.2(N2) R27.1(N1)
N16759530: C513.1(P) U5.7(COMP)
N16759616: Q6.4(G) R12.2(N2) R15.1(N1)
N16759816: Q3.4(G) R6.2(N2) R9.1(N1)
N16759886: Q14.4(G) R20.2(N2) R21.1(N1)
N16770317: R8.2(N2) R14.2(N2) U4.16(HG)
N16770321: Q2.4(G) R5.2(N2) R8.1(N1)
N16770427: C39.2(N) C511.2(N) R44.2(N2) R49.1(N1) R53.2(N2) U4.1(VIN)
N16770503: R19.2(N2) R26.2(N2) U4.12(LG)
N16770511: Q11.4(G) R18.2(N2) R19.1(N1)
N16770587: C508.2(N) D2.2(P2) U4.13(VCC)
N16770743: Q5.4(G) R11.2(N2) R14.1(N1)
N16770783: C505.2(N) D2.1(P1) U4.14(BOOT)
N16770949: C47.1(P) R44.1(N1) U4.2(RON)
N16770971: D5.2(A) R53.1(N1) R56.2(N2) R65.2(N2)
N16771247: R56.1(N1) U4.3(UDIM)
N16771311: Q10.4(G) R23.2(N2) R26.1(N1)
N16771351: R60.2(N2) R61.2(N2) U4.4(VOUT)
N16771499: C22.1(P) R32.2(N2) U4.11(CS)
N16771603: C514.1(P) U4.7(COMP)
N16778292: R7.2(N2) R13.2(N2) U3.16(HG)
N16778294: Q1.4(G) R1.2(N2) R7.1(N1)
N16778347: C36.2(N) C512.2(N) R43.2(N2) R48.1(N1) R52.2(N2) U3.1(VIN)
N16778385: R17.2(N2) R25.2(N2) U3.12(LG)
N16778389: Q8.4(G) R16.2(N2) R17.1(N1)
N16778424: C509.2(N) D1.2(P2) U3.13(VCC)
N16778502: Q4.4(G) R10.2(N2) R13.1(N1)
N16778522: C506.2(N) D1.1(P1) U3.14(BOOT)
N16778605: C46.1(P) R43.1(N1) U3.2(RON)
N16778616: D4.2(A) R52.1(N1) R55.2(N2) R64.2(N2)
N16778754: R55.1(N1) U3.3(UDIM)
N16778786: Q7.4(G) R22.2(N2) R25.1(N1)
N16778806: R58.2(N2) R59.2(N2) U3.4(VOUT)
N16778880: C20.1(P) R31.2(N2) U3.11(CS)
N16778932: C515.1(P) U3.7(COMP)
N16818658: C28.2(N) R35.1(N1) U6.2(S1A)
N16819051: C27.2(N) R34.1(N1) U6.5(S1B)
N16819694: C44.2(N) R51.1(N1) U6.11(S1C)
N16860844: R37.2(N2) U4.9(SDRV)
N16860848: Q12.4(G) R37.1(N1) R40.2(N2)
N16861238: Q9.4(G) R36.1(N1) R39.2(N2)
N16861250: R36.2(N2) U3.9(SDRV)
N16861389: Q15.4(G) R38.1(N1) R41.2(N2)
N16861401: R38.2(N2) U5.9(SDRV)
N16866899: R70.2(N2) U9.1
N16867992: R67.2(N2) U7.1
N16869200: R68.2(N2) U8.1
N16875958: R507.2(N2) U5.5(VREF)
N16876064: R508.2(N2) U4.5(VREF)
N16876097: R509.2(N2) U3.5(VREF)

Not connected (* = marked no-connect by the designer): J4 11* 12* 13* 15*; U6 12(DD) 13(S2D) 14(S1D)

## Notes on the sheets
sheet 1
- I/O CONNECTORS
sheet 2
- BLUE LED  31.6V 10A
- GREEN LED  15.8V 10A
- 31.6V 10A
- 15.8V 10A
- 10A
- 10A
- RED LED  14.2V 10A
- 14.2V 10A
- 10A
- DLP LED DRIVER
sheet 3
- Input Signals
- Independent Illuminator MUX
- LED Power Connectors
- 44V-48V INPUT
- 20A  MAX VIN
  20A MAX GND
- Mounting Holes
- INPUT, POWER, MUX
sheet 4
- B
- UPDATED ENABLE SIGNAL CONNECTION
- 02/25/20
- C
- D
- DLP LED DRIVER
  TIDA - 080008
- ESD – DWG# 2516491  / ECO# 2177981
  PCB – DWG# 2516492 / ECO# 2177982
  CCA – DWG# 2516493 / ECO# 2177983
